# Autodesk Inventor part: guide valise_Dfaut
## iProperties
Created: 2007-07
Part Number: guide valise_Dfaut
Document SubType Name: Modeling
Designer: EF
Density: 1 g/cm^3
Author: EF
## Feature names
1. Base1
